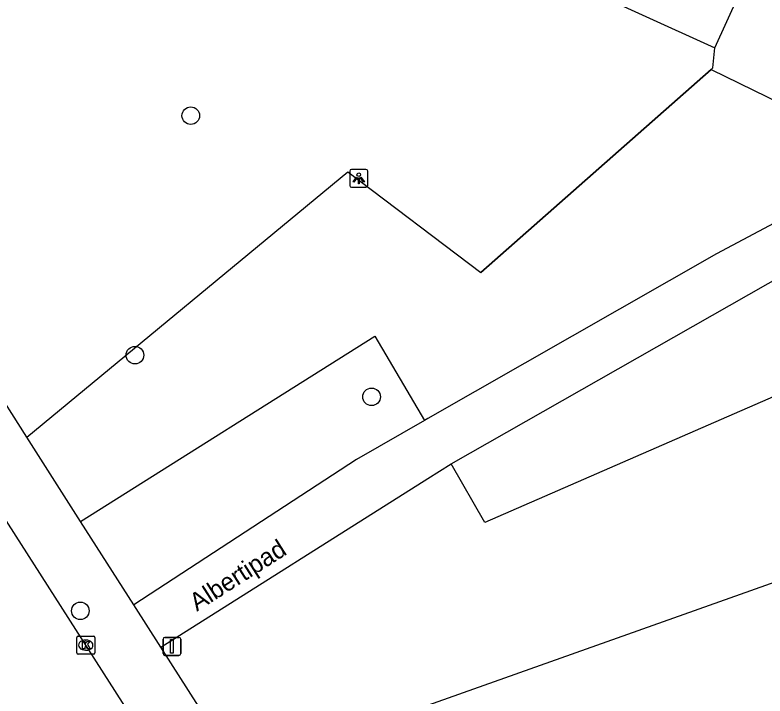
# Model space of a CAD drawing. Extents: x 159353 to 160616, y 385893 to 387321.
# Drawn here: x 159477.01 to 159518.76, y 386433.02 to 386470.95 of the extents above; entities that cross this region are included whole.
import ezdxf

# ---------------------------------------------------------------- set-up
doc = ezdxf.new("R2010")
doc.units = 0
for name, color, linetype in [('IMGEO_Boom', 7, 'Continuous'), ('IMGEO_Fietspad_gesloten', 7, 'Continuous'), ('IMGEO_Groenvoorziening', 7, 'Continuous'), ('IMGEO_Hek', 7, 'Continuous'), ('IMGEO_Kolk', 7, 'Continuous'), ('IMGEO_Lichtpunt', 7, 'Continuous'), ('IMGEO_Openbare_ruimte_label', 7, 'Continuous'), ('IMGEO_Parkeervlak_halfverhard', 7, 'Continuous'), ('IMGEO_Rijbaan_lokaal_gesloten', 7, 'Continuous'), ('IMGEO_Verkeersbordpaal', 7, 'Continuous'), ('IMGEO_Voetpad_halfverhard', 7, 'Continuous'), ('IMGEO_Voetpad_open', 7, 'Continuous')]:
    doc.layers.add(name, color=color, linetype=linetype)

msp = doc.modelspace()

# ---------------------------------------------------------------- linework, layer by layer
at = {"layer": 'IMGEO_Boom'}
for centre in [(159486.792, 386465.342), (159483.683, 386452.001), (159496.859, 386449.682), (159480.646, 386437.763)]:
    msp.add_circle(centre, 0.489, dxfattribs=at)
at = {"layer": 'IMGEO_Fietspad_gesloten'}
for points in [[(159481.905, 386484.652), (159500, 386476.402), (159515.978, 386469.117)], [(159515.978, 386469.117), (159517.402, 386472.271)]]:
    msp.add_lwpolyline(points, dxfattribs=at)
at = {"layer": 'IMGEO_Groenvoorziening'}
for points in [[(159515.761, 386467.917), (159520.446, 386465.635), (159524.713, 386468.811)], [(159529.345, 386461.535), (159532.075, 386455.291), (159503.169, 386442.684), (159501.293, 386445.946)], [(159480.655, 386442.747), (159497.049, 386453.061), (159499.81, 386448.365)], [(159489.886, 386428.296), (159500, 386432.51), (159519.962, 386439.609), (159519.338, 386441.122), (159521.98, 386442.201), (159522.049, 386442.081), (159540.719, 386449.961), (159544.391, 386451.547)]]:
    msp.add_lwpolyline(points, dxfattribs=at)
at = {"layer": 'IMGEO_Hek'}
for points in [[(159515.761, 386467.917), (159502.941, 386456.606)], [(159515.863, 386468.007), (159515.761, 386467.917)]]:
    msp.add_lwpolyline(points, dxfattribs=at)
at = {"layer": 'IMGEO_Kolk'}
for p, q in [((159480.445, 386435.426), (159480.445, 386436.278)), ((159480.52, 386436.352), (159481.372, 386436.352)), ((159480.933, 386436.132), (159480.958, 386436.132)), ((159481.446, 386436.278), (159481.446, 386435.426)), ((159480.956, 386435.572), (159480.931, 386435.572)), ((159481.372, 386435.352), (159480.52, 386435.352))]:
    msp.add_line(p, q, dxfattribs=at)
for points in [[(159480.445, 386435.426), (159480.445, 386436.278)], [(159480.52, 386436.352), (159481.372, 386436.352)], [(159480.766, 386436.052), (159480.889, 386436.052), (159480.889, 386435.901), (159481.019, 386436.052), (159481.183, 386436.052), (159481.037, 386435.901), (159481.19, 386435.652), (159481.038, 386435.652), (159480.953, 386435.816), (159480.889, 386435.749), (159480.889, 386435.652), (159480.766, 386435.652), (159480.766, 386436.052)], [(159481.446, 386436.278), (159481.446, 386435.426)], [(159481.372, 386435.352), (159480.52, 386435.352)]]:
    msp.add_lwpolyline(points, dxfattribs=at)
for centre, start, end in [((159480.522, 386436.276), 91.552, 178.448), ((159480.522, 386436.276), 91.552, 178.448), ((159481.37, 386436.276), 1.552, 88.448), ((159481.37, 386436.276), 1.552, 88.448), ((159480.522, 386435.428), 181.552, 268.448), ((159480.522, 386435.428), 181.552, 268.448), ((159481.37, 386435.428), 271.552, 358.448), ((159481.37, 386435.428), 271.552, 358.448)]:
    msp.add_arc(centre, 0.0765, start, end, dxfattribs=at)
for centre, major_axis, ratio, start_param, end_param in [((159480.932, 386435.852), (-0.387, 0.002), 0.722429, 4.712389, 7.853982), ((159480.957, 386435.852), (-0.39, 0.002), 0.717154, 1.570796, 4.712389)]:
    msp.add_ellipse(centre, major_axis=major_axis, ratio=ratio, start_param=start_param, end_param=end_param, dxfattribs=at)
at = {"layer": 'IMGEO_Lichtpunt'}
for p, q in [((159495.646, 386462.257), (159495.646, 386461.45)), ((159495.646, 386462.257), (159495.646, 386461.45)), ((159496.548, 386462.352), (159495.74, 386462.352)), ((159496.548, 386462.352), (159495.74, 386462.352)), ((159496.642, 386461.45), (159496.642, 386462.257)), ((159496.642, 386461.45), (159496.642, 386462.257)), ((159495.74, 386461.356), (159496.548, 386461.356)), ((159495.74, 386461.356), (159496.548, 386461.356))]:
    msp.add_line(p, q, dxfattribs=at)
for points in [[(159496.02, 386461.921), (159496.059, 386461.893), (159495.871, 386461.631), (159495.833, 386461.658), (159496.02, 386461.921)], [(159496.122, 386461.873), (159496.169, 386461.873), (159496.169, 386461.551), (159496.122, 386461.551), (159496.122, 386461.873)], [(159496.232, 386461.893), (159496.27, 386461.92), (159496.457, 386461.658), (159496.418, 386461.63), (159496.232, 386461.893)]]:
    msp.add_lwpolyline(points, dxfattribs=at)
msp.add_circle((159496.145, 386462.055), 0.0994, dxfattribs=at)
for centre, start, end in [((159495.74, 386462.257), 90, 180), ((159495.74, 386462.257), 90, 180), ((159496.548, 386462.257), 0, 90), ((159496.548, 386462.257), 0, 90), ((159495.74, 386461.45), 180, 270), ((159495.74, 386461.45), 180, 270), ((159496.548, 386461.45), 270, 0), ((159496.548, 386461.45), 270, 360)]:
    msp.add_arc(centre, 0.0946, start, end, dxfattribs=at)
at = {"layer": 'IMGEO_Parkeervlak_halfverhard'}
for points in [[(159515.761, 386467.917), (159515.863, 386468.007), (159515.978, 386469.117)], [(159477.671, 386447.442), (159495.539, 386462.217), (159502.941, 386456.606), (159515.761, 386467.917)]]:
    msp.add_lwpolyline(points, dxfattribs=at)
at = {"layer": 'IMGEO_Rijbaan_lokaal_gesloten'}
msp.add_lwpolyline([(159515.604, 386381.536), (159500.36, 386405.492), (159500, 386406.055), (159471.301, 386450.928)], dxfattribs=at)
at = {"layer": 'IMGEO_Verkeersbordpaal'}
for p, q in [((159485.247, 386435.384), (159485.247, 386436.184)), ((159485.247, 386436.184), (159485.247, 386435.384)), ((159485.347, 386436.284), (159486.137, 386436.284)), ((159486.137, 386436.284), (159485.347, 386436.284)), ((159486.237, 386436.184), (159486.237, 386435.384)), ((159486.237, 386435.384), (159486.237, 386436.184)), ((159486.137, 386435.284), (159485.347, 386435.284)), ((159485.347, 386435.284), (159486.137, 386435.284))]:
    msp.add_line(p, q, dxfattribs=at)
msp.add_lwpolyline([(159485.667, 386436.159), (159485.817, 386436.159), (159485.817, 386435.409), (159485.667, 386435.409), (159485.667, 386436.159)], dxfattribs=at)
for centre, start, end in [((159485.347, 386436.184), 90, 180), ((159485.347, 386436.184), 90, 180), ((159486.137, 386436.184), 0, 90), ((159486.137, 386436.184), 360, 90), ((159485.347, 386435.384), 180, 270), ((159485.347, 386435.384), 180, 270), ((159486.137, 386435.384), 270, 0), ((159486.137, 386435.384), 270, 0)]:
    msp.add_arc(centre, 0.1, start, end, dxfattribs=at)
at = {"layer": 'IMGEO_Voetpad_halfverhard'}
for points in [[(159524.713, 386468.811), (159531.236, 386465.724), (159516.054, 386457.65), (159500, 386448.474), (159499.81, 386448.365)], [(159501.293, 386445.946), (159520.968, 386457.141), (159529.345, 386461.535)], [(159499.81, 386448.365), (159496.019, 386446.193), (159483.615, 386438.09)], [(159485.117, 386435.744), (159500, 386445.131), (159501.293, 386445.946)]]:
    msp.add_lwpolyline(points, dxfattribs=at)
at = {"layer": 'IMGEO_Voetpad_open'}
for points in [[(159477.671, 386447.442), (159469.559, 386460.205)], [(159480.655, 386442.747), (159477.671, 386447.442)], [(159483.615, 386438.09), (159480.655, 386442.747)], [(159485.117, 386435.744), (159483.615, 386438.09)], [(159489.886, 386428.296), (159485.117, 386435.744)]]:
    msp.add_lwpolyline(points, dxfattribs=at)

# ---------------------------------------------------------------- texts
at = {"layer": 'IMGEO_Openbare_ruimte_label'}
msp.add_text('Albertipad', height=1, rotation=32.5459, dxfattribs=at).set_placement((159487.134, 386437.709))

doc.saveas('drawing.dxf')
